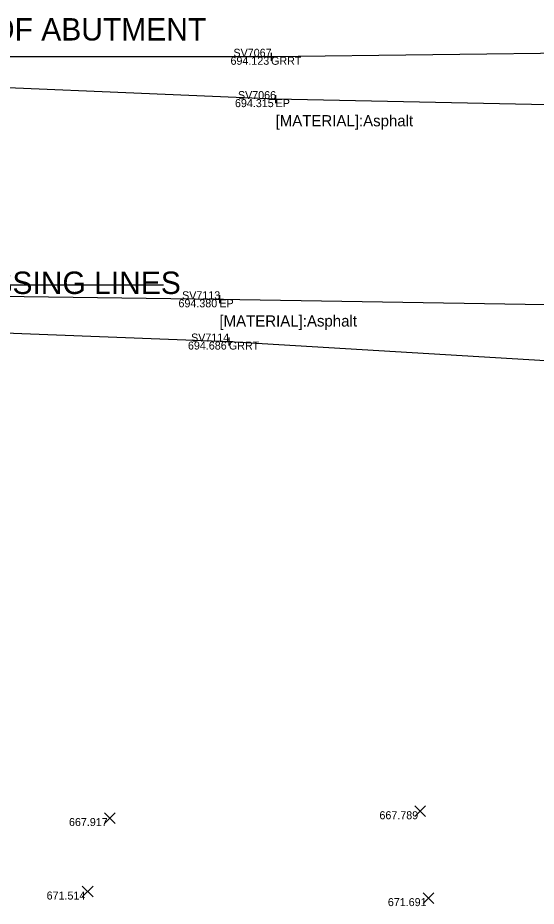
# Model space of a CAD drawing. Extents: x 1660019 to 1662995, y 619975 to 620342.
# Drawn here: x 1661570.3 to 1661635, y 620138.5 to 620249.5 of the extents above; entities that cross this region are included whole.
import ezdxf

# ---------------------------------------------------------------- set-up
doc = ezdxf.new("R2010")
doc.units = 0
for name, color, linetype in [('BR_X_Rail_Object', 7, 'Continuous'), ('PV_X_EOP', 7, 'Continuous'), ('RD_P_GR_Lt', 7, 'Continuous'), ('RD_P_GR_Rt', 7, 'Continuous'), ('RD_X_GR_Bar', 7, 'Continuous'), ('RD_X_GR_Rt', 7, 'Continuous'), ('RD_X_Wall', 7, 'Continuous'), ('SC_Scratch6', 7, 'Continuous'), ('SV_X_Text', 7, 'Continuous')]:
    doc.layers.add(name, color=color, linetype=linetype)

msp = doc.modelspace()

# ---------------------------------------------------------------- linework, layer by layer
at = {"layer": 'PV_X_EOP'}
for points in [[(1662111.67, 620229.32), (1662054.93, 620230.37), (1661998.42, 620231.32), (1661945.73, 620232.16), (1661885.47, 620233.5), (1661831.11, 620234.65), (1661773.24, 620235.9), (1661719.2, 620236.82), (1661662.34, 620238.11), (1661602.46, 620239.35), (1661551.29, 620241.52)], [(1661543.6, 620215.08), (1661595.45, 620214.35), (1661653.94, 620213.41), (1661707.72, 620212.24), (1661760.97, 620211.02), (1661840.69, 620209.32), (1661897.28, 620208.31), (1661955.8, 620207.5), (1662009.84, 620206.22), (1662063.33, 620205.17), (1662115.71, 620204.21)]]:
    msp.add_lwpolyline(points, dxfattribs=at)
at = {"layer": 'RD_P_GR_Lt'}
for p, q in [((1661601.89, 620245.14), (1661601.89, 620244.14)), ((1661601.39, 620244.64), (1661602.39, 620244.64)), ((1661601.89, 620244.64), (1661601.89, 620244.64)), ((1661601.96, 620239.35), (1661602.96, 620239.35)), ((1661602.46, 620239.85), (1661602.46, 620238.85)), ((1661602.46, 620239.35), (1661602.46, 620239.35)), ((1661594.95, 620214.35), (1661595.95, 620214.35)), ((1661595.45, 620214.85), (1661595.45, 620213.85)), ((1661595.45, 620214.35), (1661595.45, 620214.35)), ((1661596.63, 620209.57), (1661596.63, 620208.57)), ((1661596.13, 620209.07), (1661597.13, 620209.07)), ((1661596.63, 620209.07), (1661596.63, 620209.07))]:
    msp.add_line(p, q, dxfattribs=at)
at = {"layer": 'RD_P_GR_Rt'}
for p, q in [((1661619.83, 620149.74), (1661621.17, 620151.07)), ((1661619.83, 620151.07), (1661621.17, 620149.74)), ((1661581.09, 620148.89), (1661582.43, 620150.23)), ((1661581.09, 620150.23), (1661582.43, 620148.89)), ((1661578.33, 620139.72), (1661579.67, 620141.05)), ((1661578.33, 620141.05), (1661579.67, 620139.72)), ((1661620.89, 620138.89), (1661622.22, 620140.23)), ((1661620.89, 620140.23), (1661622.22, 620138.89))]:
    msp.add_line(p, q, dxfattribs=at)
at = {"layer": 'RD_X_GR_Rt'}
for points in [[(1662112.15, 620237.06), (1662055.66, 620238.25), (1661999.68, 620239.27), (1661943.73, 620240.2), (1661887.33, 620241.47), (1661831.01, 620242.22), (1661774.89, 620243.8), (1661718.6, 620244.37), (1661662.44, 620245.38), (1661601.89, 620244.64), (1661537.84, 620244.62)], [(1661527.71, 620211.76), (1661596.63, 620209.07), (1661652.77, 620205.71), (1661709.09, 620204.45), (1661758.9, 620203.47), (1661840.54, 620201.81), (1661896.27, 620200.97), (1661955.33, 620199.48), (1662008.56, 620198.59), (1662063.03, 620197.38), (1662114.92, 620196.42)]]:
    msp.add_lwpolyline(points, dxfattribs=at)
at = {"layer": 'SC_Scratch6'}
msp.add_line((1661547.5, 620216.17), (1661588.46, 620216.17), dxfattribs=at)

# ---------------------------------------------------------------- texts
at = {"layer": 'BR_X_Rail_Object'}
for s, p in [('GRRT', (1661601.89, 620243.64)), ('EP', (1661602.46, 620238.35)), ('EP', (1661595.45, 620213.35)), ('GRRT', (1661596.63, 620208.07))]:
    msp.add_text(s, height=1, dxfattribs=at).set_placement(p)
at = {"layer": 'RD_X_GR_Bar'}
for s, p in [('694.123', (1661596.83, 620243.64)), ('694.315', (1661597.39, 620238.35)), ('694.380', (1661590.34, 620213.35)), ('694.686', (1661591.52, 620208.07)), ('667.917', (1661576.67, 620148.56)), ('667.789', (1661615.42, 620149.41)), ('671.514', (1661573.88, 620139.38)), ('671.691', (1661616.47, 620138.56))]:
    msp.add_text(s, height=1, dxfattribs=at).set_placement(p)
at = {"layer": 'RD_X_Wall'}
for s, p in [('SV7067', (1661597.2, 620244.64)), ('SV7066', (1661597.76, 620239.35)), ('SV7113', (1661590.79, 620214.35)), ('SV7114', (1661591.91, 620209.07))]:
    msp.add_text(s, height=1, dxfattribs=at).set_placement(p)
at = {"layer": 'SC_Scratch6'}
for s, p in [('MISSING OUTLINE OF ABUTMENT', (1661532.85, 620246.67)), ('FIX CROSSING LINES', (1661551.93, 620215.01))]:
    msp.add_text(s, height=2.8, dxfattribs=at).set_placement(p)
at = {"layer": 'SV_X_Text'}
for p in [(1661602.46, 620235.95), (1661595.45, 620210.95)]:
    msp.add_text('[MATERIAL]:Asphalt', height=1.4, dxfattribs=at).set_placement(p)

doc.saveas('drawing.dxf')
